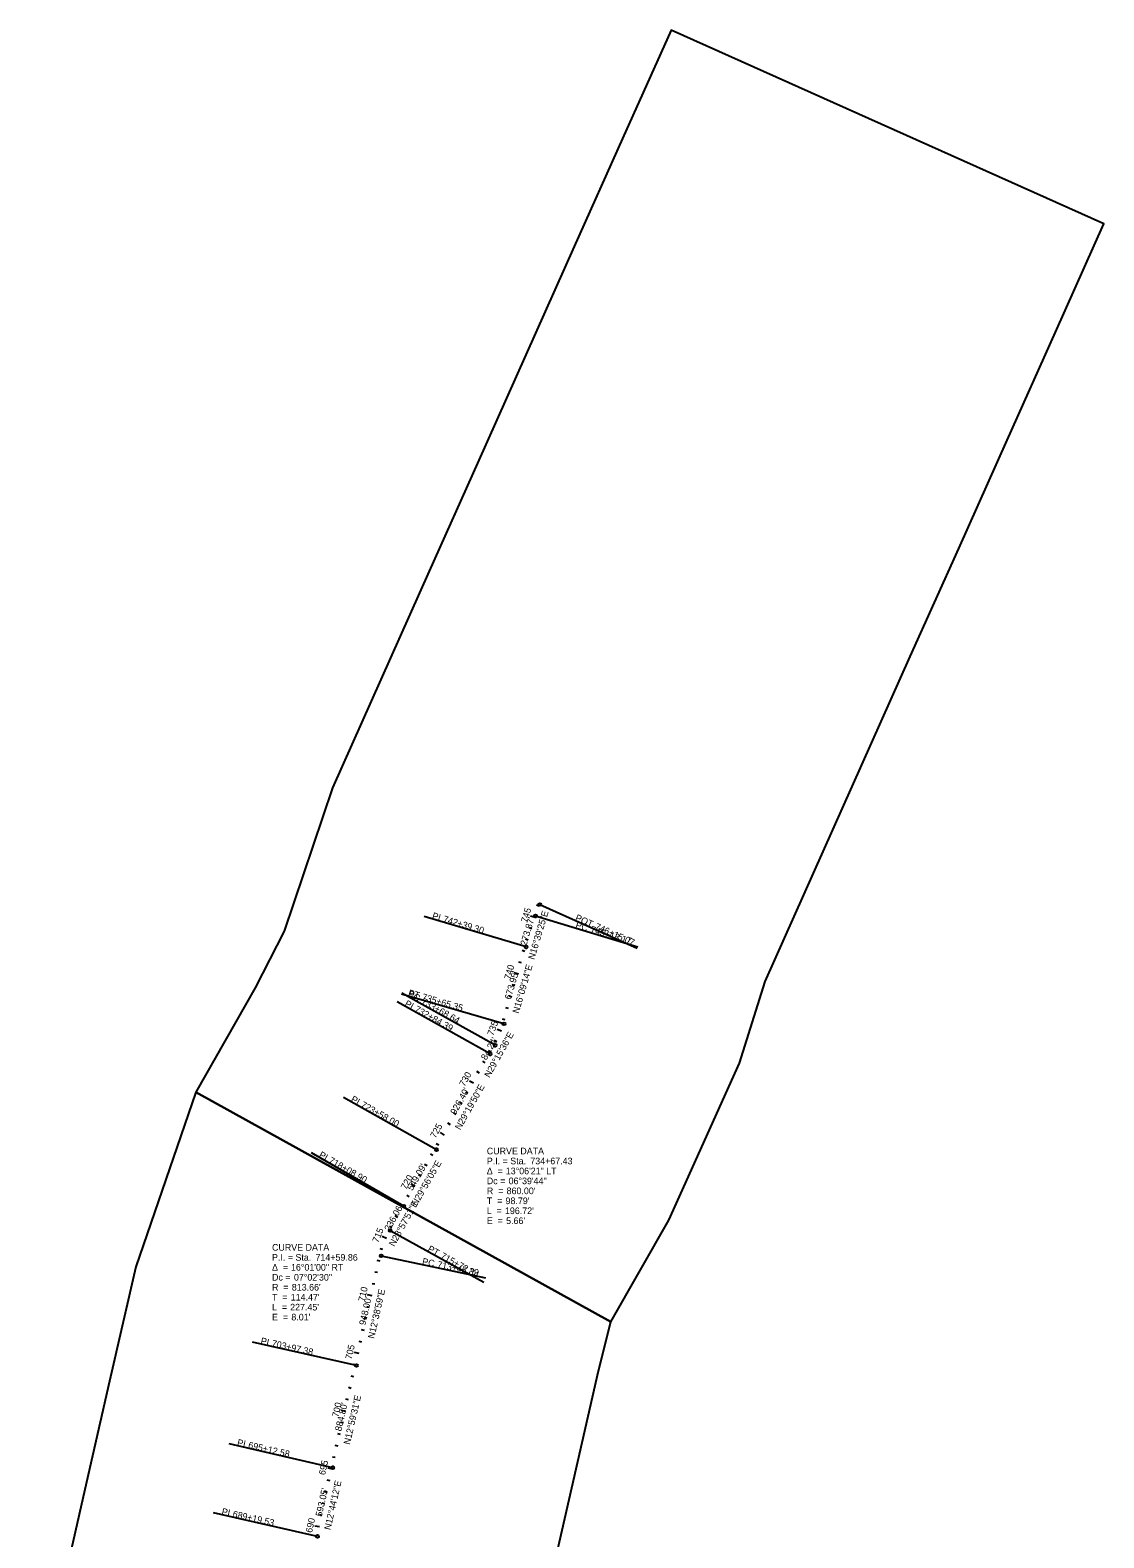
# Model space of a CAD drawing. Extents: x 1697889 to 1709091, y 242468 to 292801.
# Drawn here: x 1700032 to 1709091, y 280084 to 292801 of the extents above; entities that cross this region are included whole.
import ezdxf

# ---------------------------------------------------------------- set-up
doc = ezdxf.new("R2010")
doc.units = 0
for name, color, linetype in [('RD_P_Cells', 7, 'Continuous'), ('SC_Scratch1', 7, 'Continuous'), ('XS_P_Finished_Grade', 7, 'Continuous'), ('XS_P_Headwall', 7, 'Continuous'), ('XS_P_Pavt_Surface', 7, 'Continuous'), ('XS_P_Shoulder_Layers', 7, 'Continuous')]:
    doc.layers.add(name, color=color, linetype=linetype)

msp = doc.modelspace()

# ---------------------------------------------------------------- linework, layer by layer
at = {"layer": 'SC_Scratch1'}
for points in [[(1701431, 283843), (1704931, 281906), (1705420, 282764), (1706017, 284089), (1706233, 284778), (1706641, 285691), (1707050, 286604), (1707458, 287517), (1707866, 288430), (1708274, 289343), (1708682, 290255), (1709091, 291168), (1705439, 292801), (1705031, 291888), (1704623, 290975), (1704214, 290062), (1703806, 289150), (1703398, 288237), (1702990, 287324), (1702582, 286411), (1702175, 285202), (1701932, 284723)], [(1701146, 273330), (1705144, 273201), (1705177, 274246), (1704918, 275750), (1704664, 276717), (1704104, 278079), (1703936, 277595), (1704158, 278564), (1704379, 279532), (1704601, 280506), (1704826, 281493), (1704931, 281906), (1701431, 283843), (1700923, 282369), (1700703, 281405), (1700481, 280429), (1700257, 279448), (1700032, 278466), (1700585, 276177), (1700795, 275702), (1701049, 274735), (1701177, 274284)]]:
    msp.add_lwpolyline(points, close=True, dxfattribs=at)
at = {"layer": 'XS_P_Finished_Grade'}
for p, q in [((1704332, 285426), (1705153, 285058)), ((1704218, 285068), (1703356, 285326)), ((1704296, 285330), (1705158, 285070)), ((1703913, 284166), (1703128, 284606)), ((1704030, 284420), (1703166, 284671)), ((1703955, 284239), (1703169, 284679)), ((1703460, 283358), (1702675, 283799)), ((1703186, 282882), (1702406, 283331)), ((1703071, 282676), (1703859, 282240)), ((1702994, 282463), (1703875, 282277)), ((1702786, 281538), (1701908, 281735)), ((1702587, 280676), (1701710, 280878)), ((1702457, 280097), (1701579, 280296))]:
    msp.add_line(p, q, dxfattribs=at)
for centre in [(1704332, 285426), (1704296, 285330), (1704218, 285068), (1704030, 284420), (1703955, 284239), (1703913, 284166), (1703460, 283358), (1703186, 282882), (1703071, 282676), (1702994, 282463), (1702786, 281538), (1702587, 280676), (1702457, 280097)]:
    msp.add_circle(centre, 12, dxfattribs=at)
at = {"layer": 'XS_P_Headwall'}
for p, q in [((1704326, 285412), (1704304, 285421)), ((1704293, 285317), (1704254, 285329)), ((1704235, 285126), (1704212, 285133)), ((1704264, 285222), (1704241, 285229)), ((1704207, 285030), (1704184, 285037)), ((1704179, 284934), (1704156, 284941)), ((1704123, 284742), (1704100, 284749)), ((1704151, 284838), (1704113, 284849)), ((1704096, 284646), (1704073, 284652)), ((1704068, 284550), (1704045, 284556)), ((1704010, 284358), (1703972, 284372)), ((1704040, 284454), (1704017, 284460)), ((1703969, 284267), (1703948, 284278)), ((1703872, 284092), (1703851, 284104)), ((1703921, 284179), (1703900, 284191)), ((1703823, 284005), (1703802, 284017)), ((1703725, 283831), (1703704, 283842)), ((1703774, 283918), (1703739, 283937)), ((1703676, 283744), (1703655, 283755)), ((1703627, 283656), (1703606, 283668)), ((1703529, 283482), (1703494, 283502)), ((1703578, 283569), (1703557, 283581)), ((1703480, 283395), (1703459, 283407)), ((1703381, 283221), (1703360, 283233)), ((1703431, 283308), (1703410, 283320)), ((1703331, 283135), (1703310, 283147)), ((1703231, 282961), (1703210, 282973)), ((1703281, 283048), (1703246, 283068)), ((1703181, 282875), (1703160, 282886)), ((1703084, 282700), (1703063, 282711)), ((1703133, 282787), (1703112, 282799)), ((1703040, 282610), (1703003, 282626)), ((1703007, 282516), (1702984, 282522)), ((1702962, 282321), (1702939, 282326)), ((1702984, 282418), (1702961, 282424)), ((1702940, 282223), (1702917, 282228)), ((1702918, 282126), (1702879, 282134)), ((1702874, 281931), (1702851, 281936)), ((1702896, 282028), (1702873, 282033)), ((1702853, 281833), (1702829, 281838)), ((1702831, 281735), (1702807, 281741)), ((1702809, 281638), (1702770, 281647)), ((1702764, 281443), (1702741, 281448)), ((1702787, 281540), (1702763, 281545)), ((1702742, 281345), (1702719, 281351)), ((1702719, 281248), (1702696, 281253)), ((1702675, 281053), (1702651, 281058)), ((1702697, 281150), (1702658, 281159)), ((1702652, 280956), (1702629, 280961)), ((1702630, 280858), (1702606, 280864)), ((1702585, 280663), (1702546, 280672)), ((1702607, 280761), (1702584, 280766)), ((1702563, 280566), (1702539, 280571)), ((1702541, 280468), (1702517, 280473)), ((1702518, 280371), (1702495, 280376)), ((1702474, 280176), (1702435, 280184)), ((1702496, 280273), (1702473, 280278))]:
    msp.add_line(p, q, dxfattribs=at)

# ---------------------------------------------------------------- texts
at = {"layer": 'RD_P_Cells'}
for s, p in [('CURVE DATA', (1703885, 283319)), ('Δ  = ', (1703885, 283151)), ('P.I. = Sta. ', (1703885, 283235)), ('13°06\'21" LT', (1704045, 283151)), ('734+67.43', (1704252, 283235)), ('Dc = ', (1703885, 283067)), ('06°39\'44"', (1704069, 283067)), ('T  = ', (1703885, 282899)), ('R  = ', (1703885, 282983)), ("98.79'", (1704043, 282899)), ("860.00'", (1704052, 282983)), ('L  = ', (1703885, 282815)), ("196.72'", (1704038, 282815)), ('E  = ', (1703885, 282731)), ("5.66'", (1704048, 282731)), ('CURVE DATA', (1702073, 282506)), ('P.I. = Sta. ', (1702073, 282422)), ('714+59.86', (1702440, 282422)), ('Δ  = ', (1702073, 282338)), ('16°01\'00" RT', (1702233, 282338)), ('Dc = ', (1702073, 282254)), ('R  = ', (1702073, 282170)), ("813.66'", (1702240, 282170)), ('07°02\'30"', (1702258, 282254)), ('T  = ', (1702073, 282086)), ("114.47'", (1702231, 282086)), ('L  = ', (1702073, 282002)), ('E  = ', (1702073, 281918)), ("227.45'", (1702226, 282002)), ("8.01'", (1702236, 281918))]:
    msp.add_text(s, height=56, dxfattribs=at).set_placement(p)
at = {"layer": 'XS_P_Finished_Grade'}
for s, rotation, p in [('PI', 343.343, (1703419, 285308)), ('742+39.30', 343.343, (1703511, 285280)), ('POT', 335.9082, (1704626, 285295)), ('PC', 343.1744, (1704629, 285230)), ('745+13.17', 343.1744, (1704754, 285193)), ('746+15.07', 335.9082, (1704792, 285221)), ('PI', 330.7401, (1703187, 284574)), ('PC', 330.7401, (1703213, 284656)), ('PT', 343.846, (1703217, 284657)), ('733+68.64', 330.7401, (1703327, 284592)), ('735+65.35', 343.846, (1703333, 284623)), ('732+84.39', 330.7401, (1703270, 284527)), ('PI', 330.6695, (1702733, 283768)), ('723+58.00', 330.6695, (1702816, 283721)), ('PI', 330.0652, (1702463, 283299)), ('718+08.90', 330.0652, (1702546, 283252)), ('PC', 348.0755, (1703336, 282391)), ('PT', 331.0358, (1703381, 282505)), ('715+72.84', 331.0358, (1703488, 282446)), ('713+45.39', 348.0755, (1703463, 282365)), ('PI', 347.3504, (1701973, 281721)), ('703+97.38', 347.3504, (1702066, 281700)), ('PI', 347.0081, (1701775, 280864)), ('695+12.58', 347.0081, (1701868, 280842)), ('PI', 347.2632, (1701644, 280282)), ('689+19.53', 347.2632, (1701737, 280261))]:
    msp.add_text(s, height=56, rotation=rotation, dxfattribs=at).set_placement(p)
at = {"layer": 'XS_P_Headwall'}
for s, rotation, p in [('745', 73.343, (1704225, 285269)), ('740', 73.846, (1704084, 284789)), ('735', 69.4919, (1703939, 284315)), ('730', 60.6695, (1703697, 283886)), ('725', 60.6695, (1703452, 283450)), ('720', 60.0652, (1703204, 283017)), ('715', 67.1881, (1702968, 282569)), ('710', 77.3504, (1702854, 282073)), ('705', 77.3504, (1702745, 281585)), ('700', 77.0081, (1702633, 281098)), ('695', 77.2632, (1702520, 280610)), ('690', 77.2632, (1702410, 280123))]:
    msp.add_text(s, height=56, rotation=rotation, dxfattribs=at).set_placement(p)
at = {"layer": 'XS_P_Pavt_Surface'}
for s, rotation, p in [('N16°39\'25"E', 73.343, (1704285, 284957)), ('N16°09\'14"E', 73.846, (1704154, 284503)), ('N29°15\'36"E', 60.7401, (1703908, 283961)), ('N29°19\'50"E', 60.6695, (1703661, 283520)), ('N29°56\'05"E', 60.0652, (1703294, 282879)), ('N28°57\'51"E', 61.0358, (1703104, 282537)), ('N12°38\'59"E', 77.3504, (1702935, 281761)), ('N12°59\'31"E', 77.0081, (1702730, 280867)), ('N12°44\'12"E', 77.2632, (1702566, 280147))]:
    msp.add_text(s, height=56, rotation=rotation, dxfattribs=at).set_placement(p)
at = {"layer": 'XS_P_Shoulder_Layers'}
for s, rotation, p in [("273.87'", 73.343, (1704219, 285075)), ("673.95'", 73.846, (1704087, 284620)), ("84.24'", 60.7401, (1703880, 284109)), ("926.40'", 60.6695, (1703622, 283649)), ("549.09'", 60.0652, (1703257, 283008)), ("236.06'", 61.0358, (1703065, 282666)), ("948.00'", 77.3504, (1702861, 281874)), ("884.80'", 77.0081, (1702657, 280980)), ("593.05'", 77.2632, (1702493, 280260))]:
    msp.add_text(s, height=56, rotation=rotation, dxfattribs=at).set_placement(p)

doc.saveas('drawing.dxf')
